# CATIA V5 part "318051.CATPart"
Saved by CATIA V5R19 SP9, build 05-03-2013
Part number: 318051
Source: Unknown
Bounding box of the stored display mesh (mm): x -695.692 to 250, y 91 to 131, z 187.668 to 594
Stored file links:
  D:\16-SIL\kale oto\R19_V2\318051.CATPart
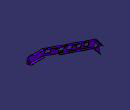
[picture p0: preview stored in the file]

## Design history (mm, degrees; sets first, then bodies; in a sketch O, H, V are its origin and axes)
Body1 "157\\122\\MANIFOLD_SOLID_BREP #72792" (main body)
  Solid1: solid without history
Body2 "241\\218\\MANIFOLD_SOLID_BREP #154205"
  Solid2: solid without history
Body3 "241\\219\\MANIFOLD_SOLID_BREP #153170"
  Solid3: solid without history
